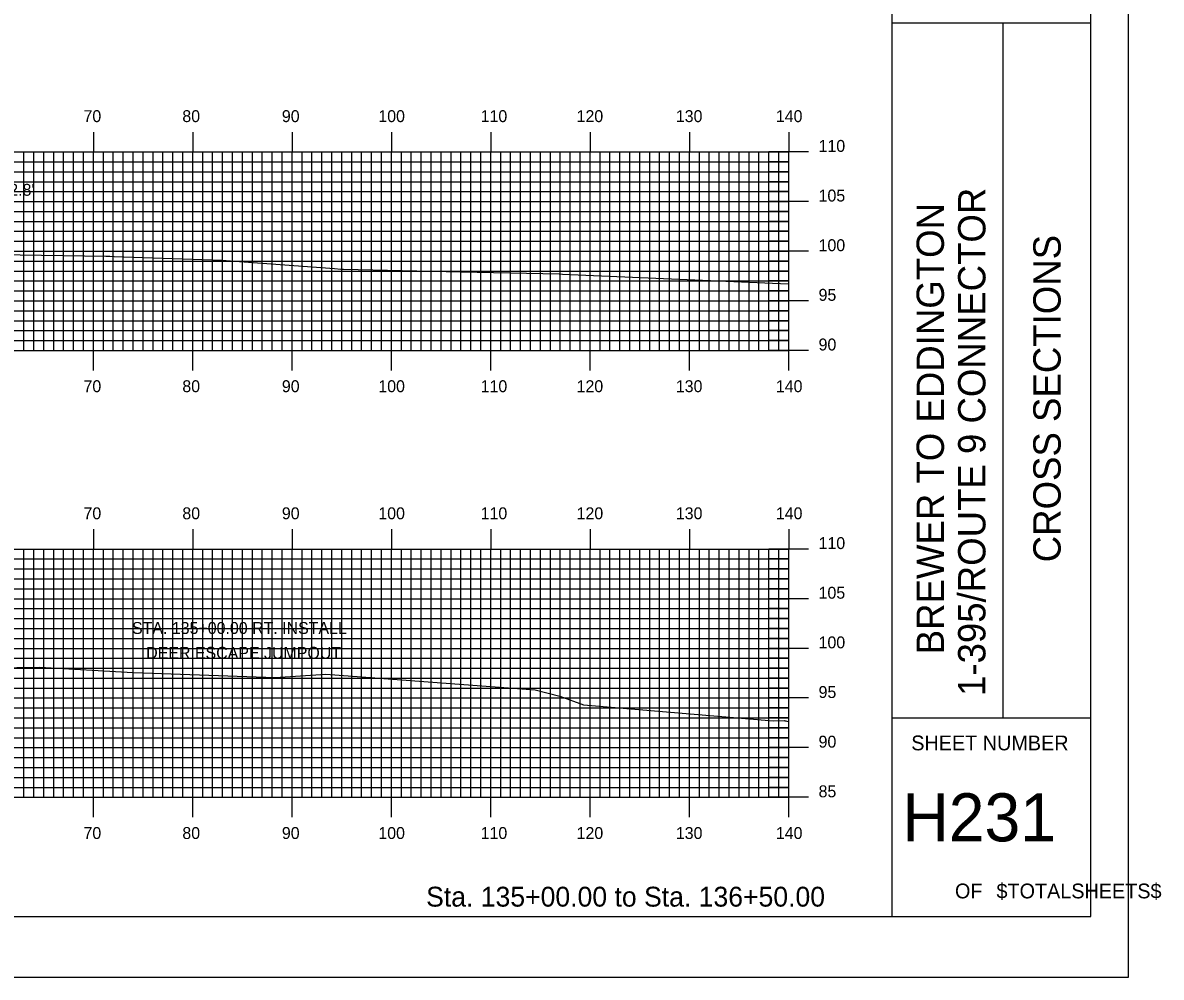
# Model space of a CAD drawing. Extents: x 1775170 to 1775514, y 442591 to 442811.
# Drawn here: x 1775399.1 to 1775513.7, y 442590.5 to 442686.7 of the extents above; entities that cross this region are included whole.
import ezdxf

# ---------------------------------------------------------------- set-up
doc = ezdxf.new("R2010")
doc.units = 0
for name, color, linetype in [('BORDER', 7, 'Continuous'), ('D_Text_Standard', 7, 'Continuous'), ('H_V ANNOTATION', 7, 'Continuous'), ('MAJOR', 7, 'Continuous'), ('MINOR', 7, 'Continuous'), ('PLOT BOUNDARY', 7, 'Continuous'), ('S_Roadway_Centerline', 7, 'Continuous')]:
    doc.layers.add(name, color=color, linetype=linetype)

msp = doc.modelspace()

# ---------------------------------------------------------------- linework, layer by layer
at = {"layer": 'BORDER'}
for p, q in [((1775486.6, 442596.67), (1775486.6, 442806.67)), ((1775486.6, 442686.67), (1775506.6, 442686.67)), ((1775497.78, 442616.67), (1775497.78, 442686.67)), ((1775486.6, 442616.67), (1775506.6, 442616.67))]:
    msp.add_line(p, q, dxfattribs=at)
msp.add_lwpolyline([(1775186.6, 442596.67), (1775506.6, 442596.67), (1775506.6, 442806.67), (1775186.6, 442806.67)], close=True, dxfattribs=at)
at = {"layer": 'MAJOR'}
for p, q in [((1775406.2, 442675.67), (1775406.2, 442673.67)), ((1775416.2, 442675.67), (1775416.2, 442673.67)), ((1775426.2, 442675.67), (1775426.2, 442673.67)), ((1775436.2, 442675.67), (1775436.2, 442673.67)), ((1775446.2, 442675.67), (1775446.2, 442673.67)), ((1775456.2, 442675.67), (1775456.2, 442673.67)), ((1775466.2, 442675.67), (1775466.2, 442673.67)), ((1775476.2, 442675.67), (1775476.2, 442673.67)), ((1775196.2, 442673.67), (1775476.2, 442673.67)), ((1775196.2, 442673.67), (1775476.2, 442673.67)), ((1775406.2, 442653.67), (1775406.2, 442673.67)), ((1775416.2, 442653.67), (1775416.2, 442673.67)), ((1775426.2, 442653.67), (1775426.2, 442673.67)), ((1775436.2, 442653.67), (1775436.2, 442673.67)), ((1775446.2, 442653.67), (1775446.2, 442673.67)), ((1775456.2, 442653.67), (1775456.2, 442673.67)), ((1775466.2, 442653.67), (1775466.2, 442673.67)), ((1775478.2, 442673.67), (1775474.19, 442673.67)), ((1775476.2, 442653.67), (1775476.2, 442673.67)), ((1775476.2, 442653.67), (1775476.2, 442673.67)), ((1775196.2, 442668.67), (1775476.2, 442668.67)), ((1775478.2, 442668.67), (1775474.19, 442668.67)), ((1775196.2, 442663.67), (1775476.2, 442663.67)), ((1775478.2, 442663.67), (1775474.19, 442663.67)), ((1775196.2, 442658.67), (1775476.2, 442658.67)), ((1775478.2, 442658.67), (1775474.19, 442658.67)), ((1775196.2, 442653.67), (1775476.2, 442653.67)), ((1775196.2, 442653.67), (1775476.2, 442653.67)), ((1775406.2, 442651.66), (1775406.2, 442653.67)), ((1775416.2, 442651.66), (1775416.2, 442653.67)), ((1775426.2, 442651.66), (1775426.2, 442653.67)), ((1775436.2, 442651.66), (1775436.2, 442653.67)), ((1775446.2, 442651.66), (1775446.2, 442653.67)), ((1775456.2, 442651.66), (1775456.2, 442653.67)), ((1775466.2, 442651.66), (1775466.2, 442653.67)), ((1775478.2, 442653.67), (1775474.19, 442653.67)), ((1775476.2, 442651.66), (1775476.2, 442653.67)), ((1775406.2, 442635.67), (1775406.2, 442633.67)), ((1775416.2, 442635.67), (1775416.2, 442633.67)), ((1775426.2, 442635.67), (1775426.2, 442633.67)), ((1775436.2, 442635.67), (1775436.2, 442633.67)), ((1775446.2, 442635.67), (1775446.2, 442633.67)), ((1775456.2, 442635.67), (1775456.2, 442633.67)), ((1775466.2, 442635.67), (1775466.2, 442633.67)), ((1775476.2, 442635.67), (1775476.2, 442633.67)), ((1775196.2, 442633.67), (1775476.2, 442633.67)), ((1775196.2, 442633.67), (1775476.2, 442633.67)), ((1775406.2, 442608.67), (1775406.2, 442633.67)), ((1775416.2, 442608.67), (1775416.2, 442633.67)), ((1775426.2, 442608.67), (1775426.2, 442633.67)), ((1775436.2, 442608.67), (1775436.2, 442633.67)), ((1775446.2, 442608.67), (1775446.2, 442633.67)), ((1775456.2, 442608.67), (1775456.2, 442633.67)), ((1775466.2, 442608.67), (1775466.2, 442633.67)), ((1775478.2, 442633.67), (1775474.19, 442633.67)), ((1775476.2, 442608.67), (1775476.2, 442633.67)), ((1775476.2, 442608.67), (1775476.2, 442633.67)), ((1775196.2, 442628.67), (1775476.2, 442628.67)), ((1775478.2, 442628.67), (1775474.19, 442628.67)), ((1775196.2, 442623.67), (1775476.2, 442623.67)), ((1775478.2, 442623.67), (1775474.19, 442623.67)), ((1775196.2, 442618.67), (1775476.2, 442618.67)), ((1775478.2, 442618.67), (1775474.19, 442618.67)), ((1775196.2, 442613.67), (1775476.2, 442613.67)), ((1775478.2, 442613.67), (1775474.19, 442613.67)), ((1775196.2, 442608.67), (1775476.2, 442608.67)), ((1775196.2, 442608.67), (1775476.2, 442608.67)), ((1775406.2, 442606.66), (1775406.2, 442608.67)), ((1775416.2, 442606.66), (1775416.2, 442608.67)), ((1775426.2, 442606.66), (1775426.2, 442608.67)), ((1775436.2, 442606.66), (1775436.2, 442608.67)), ((1775446.2, 442606.66), (1775446.2, 442608.67)), ((1775456.2, 442606.66), (1775456.2, 442608.67)), ((1775466.2, 442606.66), (1775466.2, 442608.67)), ((1775478.2, 442608.67), (1775474.19, 442608.67)), ((1775476.2, 442606.66), (1775476.2, 442608.67))]:
    msp.add_line(p, q, dxfattribs=at)
at = {"layer": 'MINOR'}
for p, q in [((1775399.2, 442653.67), (1775399.2, 442673.67)), ((1775400.2, 442653.67), (1775400.2, 442673.67)), ((1775401.2, 442653.67), (1775401.2, 442673.67)), ((1775402.2, 442653.67), (1775402.2, 442673.67)), ((1775403.2, 442653.67), (1775403.2, 442673.67)), ((1775404.2, 442653.67), (1775404.2, 442673.67)), ((1775405.2, 442653.67), (1775405.2, 442673.67)), ((1775407.2, 442653.67), (1775407.2, 442673.67)), ((1775408.2, 442653.67), (1775408.2, 442673.67)), ((1775409.2, 442653.67), (1775409.2, 442673.67)), ((1775410.2, 442653.67), (1775410.2, 442673.67)), ((1775411.2, 442653.67), (1775411.2, 442673.67)), ((1775412.2, 442653.67), (1775412.2, 442673.67)), ((1775413.2, 442653.67), (1775413.2, 442673.67)), ((1775414.2, 442653.67), (1775414.2, 442673.67)), ((1775415.2, 442653.67), (1775415.2, 442673.67)), ((1775417.2, 442653.67), (1775417.2, 442673.67)), ((1775418.2, 442653.67), (1775418.2, 442673.67)), ((1775419.2, 442653.67), (1775419.2, 442673.67)), ((1775420.2, 442653.67), (1775420.2, 442673.67)), ((1775421.2, 442653.67), (1775421.2, 442673.67)), ((1775422.2, 442653.67), (1775422.2, 442673.67)), ((1775423.2, 442653.67), (1775423.2, 442673.67)), ((1775424.2, 442653.67), (1775424.2, 442673.67)), ((1775425.2, 442653.67), (1775425.2, 442673.67)), ((1775427.2, 442653.67), (1775427.2, 442673.67)), ((1775428.2, 442653.67), (1775428.2, 442673.67)), ((1775429.2, 442653.67), (1775429.2, 442673.67)), ((1775430.2, 442653.67), (1775430.2, 442673.67)), ((1775431.2, 442653.67), (1775431.2, 442673.67)), ((1775432.2, 442653.67), (1775432.2, 442673.67)), ((1775433.2, 442653.67), (1775433.2, 442673.67)), ((1775434.2, 442653.67), (1775434.2, 442673.67)), ((1775435.2, 442653.67), (1775435.2, 442673.67)), ((1775437.2, 442653.67), (1775437.2, 442673.67)), ((1775438.2, 442653.67), (1775438.2, 442673.67)), ((1775439.2, 442653.67), (1775439.2, 442673.67)), ((1775440.2, 442653.67), (1775440.2, 442673.67)), ((1775441.2, 442653.67), (1775441.2, 442673.67)), ((1775442.2, 442653.67), (1775442.2, 442673.67)), ((1775443.2, 442653.67), (1775443.2, 442673.67)), ((1775444.2, 442653.67), (1775444.2, 442673.67)), ((1775445.2, 442653.67), (1775445.2, 442673.67)), ((1775447.2, 442653.67), (1775447.2, 442673.67)), ((1775448.2, 442653.67), (1775448.2, 442673.67)), ((1775449.2, 442653.67), (1775449.2, 442673.67)), ((1775450.2, 442653.67), (1775450.2, 442673.67)), ((1775451.2, 442653.67), (1775451.2, 442673.67)), ((1775452.2, 442653.67), (1775452.2, 442673.67)), ((1775453.2, 442653.67), (1775453.2, 442673.67)), ((1775454.2, 442653.67), (1775454.2, 442673.67)), ((1775455.2, 442653.67), (1775455.2, 442673.67)), ((1775457.2, 442653.67), (1775457.2, 442673.67)), ((1775458.2, 442653.67), (1775458.2, 442673.67)), ((1775459.2, 442653.67), (1775459.2, 442673.67)), ((1775460.2, 442653.67), (1775460.2, 442673.67)), ((1775461.2, 442653.67), (1775461.2, 442673.67)), ((1775462.2, 442653.67), (1775462.2, 442673.67)), ((1775463.2, 442653.67), (1775463.2, 442673.67)), ((1775464.2, 442653.67), (1775464.2, 442673.67)), ((1775465.2, 442653.67), (1775465.2, 442673.67)), ((1775467.2, 442653.67), (1775467.2, 442673.67)), ((1775468.2, 442653.67), (1775468.2, 442673.67)), ((1775469.2, 442653.67), (1775469.2, 442673.67)), ((1775470.2, 442653.67), (1775470.2, 442673.67)), ((1775471.2, 442653.67), (1775471.2, 442673.67)), ((1775472.2, 442653.67), (1775472.2, 442673.67)), ((1775473.2, 442653.67), (1775473.2, 442673.67)), ((1775474.2, 442653.67), (1775474.2, 442673.67)), ((1775475.2, 442653.67), (1775475.2, 442673.67)), ((1775196.2, 442672.67), (1775476.2, 442672.67)), ((1775476.2, 442672.67), (1775474.19, 442672.67)), ((1775196.2, 442671.67), (1775476.2, 442671.67)), ((1775476.2, 442671.67), (1775474.19, 442671.67)), ((1775196.2, 442670.67), (1775476.2, 442670.67)), ((1775476.2, 442670.67), (1775474.19, 442670.67)), ((1775196.2, 442669.67), (1775476.2, 442669.67)), ((1775476.2, 442669.67), (1775474.19, 442669.67)), ((1775196.2, 442667.67), (1775476.2, 442667.67)), ((1775476.2, 442667.67), (1775474.19, 442667.67)), ((1775196.2, 442666.67), (1775476.2, 442666.67)), ((1775476.2, 442666.67), (1775474.19, 442666.67)), ((1775196.2, 442665.67), (1775476.2, 442665.67)), ((1775476.2, 442665.67), (1775474.19, 442665.67)), ((1775196.2, 442664.67), (1775476.2, 442664.67)), ((1775476.2, 442664.67), (1775474.19, 442664.67)), ((1775196.2, 442662.67), (1775476.2, 442662.67)), ((1775196.2, 442661.67), (1775476.2, 442661.67)), ((1775476.2, 442662.67), (1775474.19, 442662.67)), ((1775476.2, 442661.67), (1775474.19, 442661.67)), ((1775196.2, 442660.67), (1775476.2, 442660.67)), ((1775476.2, 442660.67), (1775474.19, 442660.67)), ((1775196.2, 442659.67), (1775476.2, 442659.67)), ((1775476.2, 442659.67), (1775474.19, 442659.67)), ((1775196.2, 442657.67), (1775476.2, 442657.67)), ((1775476.2, 442657.67), (1775474.19, 442657.67)), ((1775196.2, 442656.67), (1775476.2, 442656.67)), ((1775476.2, 442656.67), (1775474.19, 442656.67)), ((1775196.2, 442655.67), (1775476.2, 442655.67)), ((1775476.2, 442655.67), (1775474.19, 442655.67)), ((1775196.2, 442654.67), (1775476.2, 442654.67)), ((1775476.2, 442654.67), (1775474.19, 442654.67)), ((1775399.2, 442608.67), (1775399.2, 442633.67)), ((1775400.2, 442608.67), (1775400.2, 442633.67)), ((1775401.2, 442608.67), (1775401.2, 442633.67)), ((1775402.2, 442608.67), (1775402.2, 442633.67)), ((1775403.2, 442608.67), (1775403.2, 442633.67)), ((1775404.2, 442608.67), (1775404.2, 442633.67)), ((1775405.2, 442608.67), (1775405.2, 442633.67)), ((1775407.2, 442608.67), (1775407.2, 442633.67)), ((1775408.2, 442608.67), (1775408.2, 442633.67)), ((1775409.2, 442608.67), (1775409.2, 442633.67)), ((1775410.2, 442608.67), (1775410.2, 442633.67)), ((1775411.2, 442608.67), (1775411.2, 442633.67)), ((1775412.2, 442608.67), (1775412.2, 442633.67)), ((1775413.2, 442608.67), (1775413.2, 442633.67)), ((1775414.2, 442608.67), (1775414.2, 442633.67)), ((1775415.2, 442608.67), (1775415.2, 442633.67)), ((1775417.2, 442608.67), (1775417.2, 442633.67)), ((1775418.2, 442608.67), (1775418.2, 442633.67)), ((1775419.2, 442608.67), (1775419.2, 442633.67)), ((1775420.2, 442608.67), (1775420.2, 442633.67)), ((1775421.2, 442608.67), (1775421.2, 442633.67)), ((1775422.2, 442608.67), (1775422.2, 442633.67)), ((1775423.2, 442608.67), (1775423.2, 442633.67)), ((1775424.2, 442608.67), (1775424.2, 442633.67)), ((1775425.2, 442608.67), (1775425.2, 442633.67)), ((1775427.2, 442608.67), (1775427.2, 442633.67)), ((1775428.2, 442608.67), (1775428.2, 442633.67)), ((1775429.2, 442608.67), (1775429.2, 442633.67)), ((1775430.2, 442608.67), (1775430.2, 442633.67)), ((1775431.2, 442608.67), (1775431.2, 442633.67)), ((1775432.2, 442608.67), (1775432.2, 442633.67)), ((1775433.2, 442608.67), (1775433.2, 442633.67)), ((1775434.2, 442608.67), (1775434.2, 442633.67)), ((1775435.2, 442608.67), (1775435.2, 442633.67)), ((1775437.2, 442608.67), (1775437.2, 442633.67)), ((1775438.2, 442608.67), (1775438.2, 442633.67)), ((1775439.2, 442608.67), (1775439.2, 442633.67)), ((1775440.2, 442608.67), (1775440.2, 442633.67)), ((1775441.2, 442608.67), (1775441.2, 442633.67)), ((1775442.2, 442608.67), (1775442.2, 442633.67)), ((1775443.2, 442608.67), (1775443.2, 442633.67)), ((1775444.2, 442608.67), (1775444.2, 442633.67)), ((1775445.2, 442608.67), (1775445.2, 442633.67)), ((1775447.2, 442608.67), (1775447.2, 442633.67)), ((1775448.2, 442608.67), (1775448.2, 442633.67)), ((1775449.2, 442608.67), (1775449.2, 442633.67)), ((1775450.2, 442608.67), (1775450.2, 442633.67)), ((1775451.2, 442608.67), (1775451.2, 442633.67)), ((1775452.2, 442608.67), (1775452.2, 442633.67)), ((1775453.2, 442608.67), (1775453.2, 442633.67)), ((1775454.2, 442608.67), (1775454.2, 442633.67)), ((1775455.2, 442608.67), (1775455.2, 442633.67)), ((1775457.2, 442608.67), (1775457.2, 442633.67)), ((1775458.2, 442608.67), (1775458.2, 442633.67)), ((1775459.2, 442608.67), (1775459.2, 442633.67)), ((1775460.2, 442608.67), (1775460.2, 442633.67)), ((1775461.2, 442608.67), (1775461.2, 442633.67)), ((1775462.2, 442608.67), (1775462.2, 442633.67)), ((1775463.2, 442608.67), (1775463.2, 442633.67)), ((1775464.2, 442608.67), (1775464.2, 442633.67)), ((1775465.2, 442608.67), (1775465.2, 442633.67)), ((1775467.2, 442608.67), (1775467.2, 442633.67)), ((1775468.2, 442608.67), (1775468.2, 442633.67)), ((1775469.2, 442608.67), (1775469.2, 442633.67)), ((1775470.2, 442608.67), (1775470.2, 442633.67)), ((1775471.2, 442608.67), (1775471.2, 442633.67)), ((1775472.2, 442608.67), (1775472.2, 442633.67)), ((1775473.2, 442608.67), (1775473.2, 442633.67)), ((1775474.2, 442608.67), (1775474.2, 442633.67)), ((1775475.2, 442608.67), (1775475.2, 442633.67)), ((1775196.2, 442632.67), (1775476.2, 442632.67)), ((1775476.2, 442632.67), (1775474.19, 442632.67)), ((1775196.2, 442631.67), (1775476.2, 442631.67)), ((1775476.2, 442631.67), (1775474.19, 442631.67)), ((1775196.2, 442630.67), (1775476.2, 442630.67)), ((1775196.2, 442629.67), (1775476.2, 442629.67)), ((1775476.2, 442630.67), (1775474.19, 442630.67)), ((1775476.2, 442629.67), (1775474.19, 442629.67)), ((1775196.2, 442627.67), (1775476.2, 442627.67)), ((1775476.2, 442627.67), (1775474.19, 442627.67)), ((1775196.2, 442626.67), (1775476.2, 442626.67)), ((1775476.2, 442626.67), (1775474.19, 442626.67)), ((1775196.2, 442625.67), (1775476.2, 442625.67)), ((1775476.2, 442625.67), (1775474.19, 442625.67)), ((1775196.2, 442624.67), (1775476.2, 442624.67)), ((1775476.2, 442624.67), (1775474.19, 442624.67)), ((1775196.2, 442622.67), (1775476.2, 442622.67)), ((1775196.2, 442621.67), (1775476.2, 442621.67)), ((1775476.2, 442622.67), (1775474.19, 442622.67)), ((1775476.2, 442621.67), (1775474.19, 442621.67)), ((1775196.2, 442620.67), (1775476.2, 442620.67)), ((1775476.2, 442620.67), (1775474.19, 442620.67)), ((1775196.2, 442619.67), (1775476.2, 442619.67)), ((1775476.2, 442619.67), (1775474.19, 442619.67)), ((1775196.2, 442617.67), (1775476.2, 442617.67)), ((1775476.2, 442617.67), (1775474.19, 442617.67)), ((1775196.2, 442616.67), (1775476.2, 442616.67)), ((1775476.2, 442616.67), (1775474.19, 442616.67)), ((1775196.2, 442615.67), (1775476.2, 442615.67)), ((1775476.2, 442615.67), (1775474.19, 442615.67)), ((1775196.2, 442614.67), (1775476.2, 442614.67)), ((1775476.2, 442614.67), (1775474.19, 442614.67)), ((1775196.2, 442612.67), (1775476.2, 442612.67)), ((1775476.2, 442612.67), (1775474.19, 442612.67)), ((1775196.2, 442611.67), (1775476.2, 442611.67)), ((1775476.2, 442611.67), (1775474.19, 442611.67)), ((1775196.2, 442610.67), (1775476.2, 442610.67)), ((1775476.2, 442610.67), (1775474.19, 442610.67)), ((1775196.2, 442609.67), (1775476.2, 442609.67)), ((1775476.2, 442609.67), (1775474.19, 442609.67))]:
    msp.add_line(p, q, dxfattribs=at)
at = {"layer": 'PLOT BOUNDARY'}
msp.add_lwpolyline([(1775170.41, 442590.55), (1775510.41, 442590.55), (1775510.41, 442810.55), (1775170.41, 442810.55)], close=True, dxfattribs=at)
at = {"layer": 'S_Roadway_Centerline'}
for points in [[(1775383.72, 442663.54), (1775407.44, 442663.17), (1775407.84, 442663.16), (1775408.29, 442663.14), (1775419.1, 442662.75), (1775430.47, 442661.91), (1775431.09, 442661.87), (1775431.38, 442661.87), (1775443.17, 442661.6), (1775453.1, 442661.38), (1775453.43, 442661.37), (1775476.14, 442660.39), (1775476.2, 442660.39)], [(1775387.02, 442621.59), (1775400.77, 442621.77), (1775410.19, 442621.24), (1775424.51, 442620.73), (1775429.61, 442621.06), (1775450.67, 442619.49), (1775453.16, 442618.84), (1775455.54, 442617.99), (1775474.64, 442616.38), (1775475.73, 442616.4), (1775475.81, 442616.38), (1775475.91, 442616.36), (1775476.01, 442616.33), (1775476.13, 442616.31), (1775476.2, 442616.3)]]:
    msp.add_lwpolyline(points, dxfattribs=at)

# ---------------------------------------------------------------- texts
at = {"layer": 'BORDER'}
for s, p in [('1-395/ROUTE 9 CONNECTOR', (1775496, 442618.87)), ('BREWER TO EDDINGTON', (1775491.82, 442623.07)), ('CROSS SECTIONS', (1775503.57, 442632.34))]:
    msp.add_text(s, height=2.7557, rotation=90, dxfattribs=at).set_placement(p)
for s, height, p in [('SHEET NUMBER', 1.4905, (1775488.53, 442613.4)), ('H231', 4.839, (1775487.63, 442604.23)), ('OF', 1.491, (1775492.93, 442598.49)), ('$TOTALSHEETS$', 1.4905, (1775497.11, 442598.49))]:
    msp.add_text(s, height=height, dxfattribs=at).set_placement(p)
at = {"layer": 'D_Text_Standard'}
for s, p in [("62.8'", (1775396.83, 442669.25)), ('STA. 135+00.00 RT. INSTALL ', (1775410.08, 442625.12)), ('DEER ESCAPE JUMPOUT', (1775411.51, 442622.62))]:
    msp.add_text(s, height=1.2, dxfattribs=at).set_placement(p)
at = {"layer": 'H_V ANNOTATION'}
for s, height, p in [('70', 1.2, (1775405.2, 442676.67)), ('80', 1.2, (1775415.15, 442676.67)), ('90', 1.2, (1775425.17, 442676.67)), ('100', 1.2, (1775434.88, 442676.67)), ('110', 1.2, (1775445.18, 442676.67)), ('120', 1.2, (1775454.84, 442676.67)), ('130', 1.2, (1775464.83, 442676.67)), ('140', 1.2, (1775474.9, 442676.67)), ('110', 1.2, (1775479.2, 442673.67)), ('105', 1.2, (1775479.2, 442668.67)), ('100', 1.2, (1775479.2, 442663.67)), ('95', 1.2, (1775479.2, 442658.67)), ('90', 1.2, (1775479.2, 442653.67)), ('70', 1.2, (1775405.2, 442649.47)), ('80', 1.2, (1775415.15, 442649.47)), ('90', 1.2, (1775425.17, 442649.47)), ('100', 1.2, (1775434.88, 442649.47)), ('110', 1.2, (1775445.18, 442649.47)), ('120', 1.2, (1775454.84, 442649.47)), ('130', 1.2, (1775464.83, 442649.47)), ('140', 1.2, (1775474.9, 442649.47)), ('70', 1.2, (1775405.2, 442636.67)), ('80', 1.2, (1775415.15, 442636.67)), ('90', 1.2, (1775425.17, 442636.67)), ('100', 1.2, (1775434.88, 442636.67)), ('110', 1.2, (1775445.18, 442636.67)), ('120', 1.2, (1775454.84, 442636.67)), ('130', 1.2, (1775464.83, 442636.67)), ('140', 1.2, (1775474.9, 442636.67)), ('110', 1.2, (1775479.2, 442633.67)), ('105', 1.2, (1775479.2, 442628.67)), ('100', 1.2, (1775479.2, 442623.67)), ('95', 1.2, (1775479.2, 442618.67)), ('90', 1.2, (1775479.2, 442613.67)), ('85', 1.2, (1775479.2, 442608.67)), ('70', 1.2, (1775405.2, 442604.47)), ('80', 1.2, (1775415.15, 442604.47)), ('90', 1.2, (1775425.17, 442604.47)), ('100', 1.2, (1775434.88, 442604.47)), ('110', 1.2, (1775445.18, 442604.47)), ('120', 1.2, (1775454.84, 442604.47)), ('130', 1.2, (1775464.83, 442604.47)), ('140', 1.2, (1775474.9, 442604.47)), ('Sta. 135+00.00 to Sta. 136+50.00', 2.0004, (1775439.69, 442597.66))]:
    msp.add_text(s, height=height, dxfattribs=at).set_placement(p)

doc.saveas('drawing.dxf')
